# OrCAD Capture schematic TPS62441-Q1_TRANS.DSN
size E; title: TPS62441-Q1 2.75-V to 6-V Dual Step-Down Converter; rev: 1.0; note: Datasheet: SLUSDN9          EVM:SLVUC33; note: Synchronous Step Down Converter; note: with Adjustable Frequency in a QFN Package
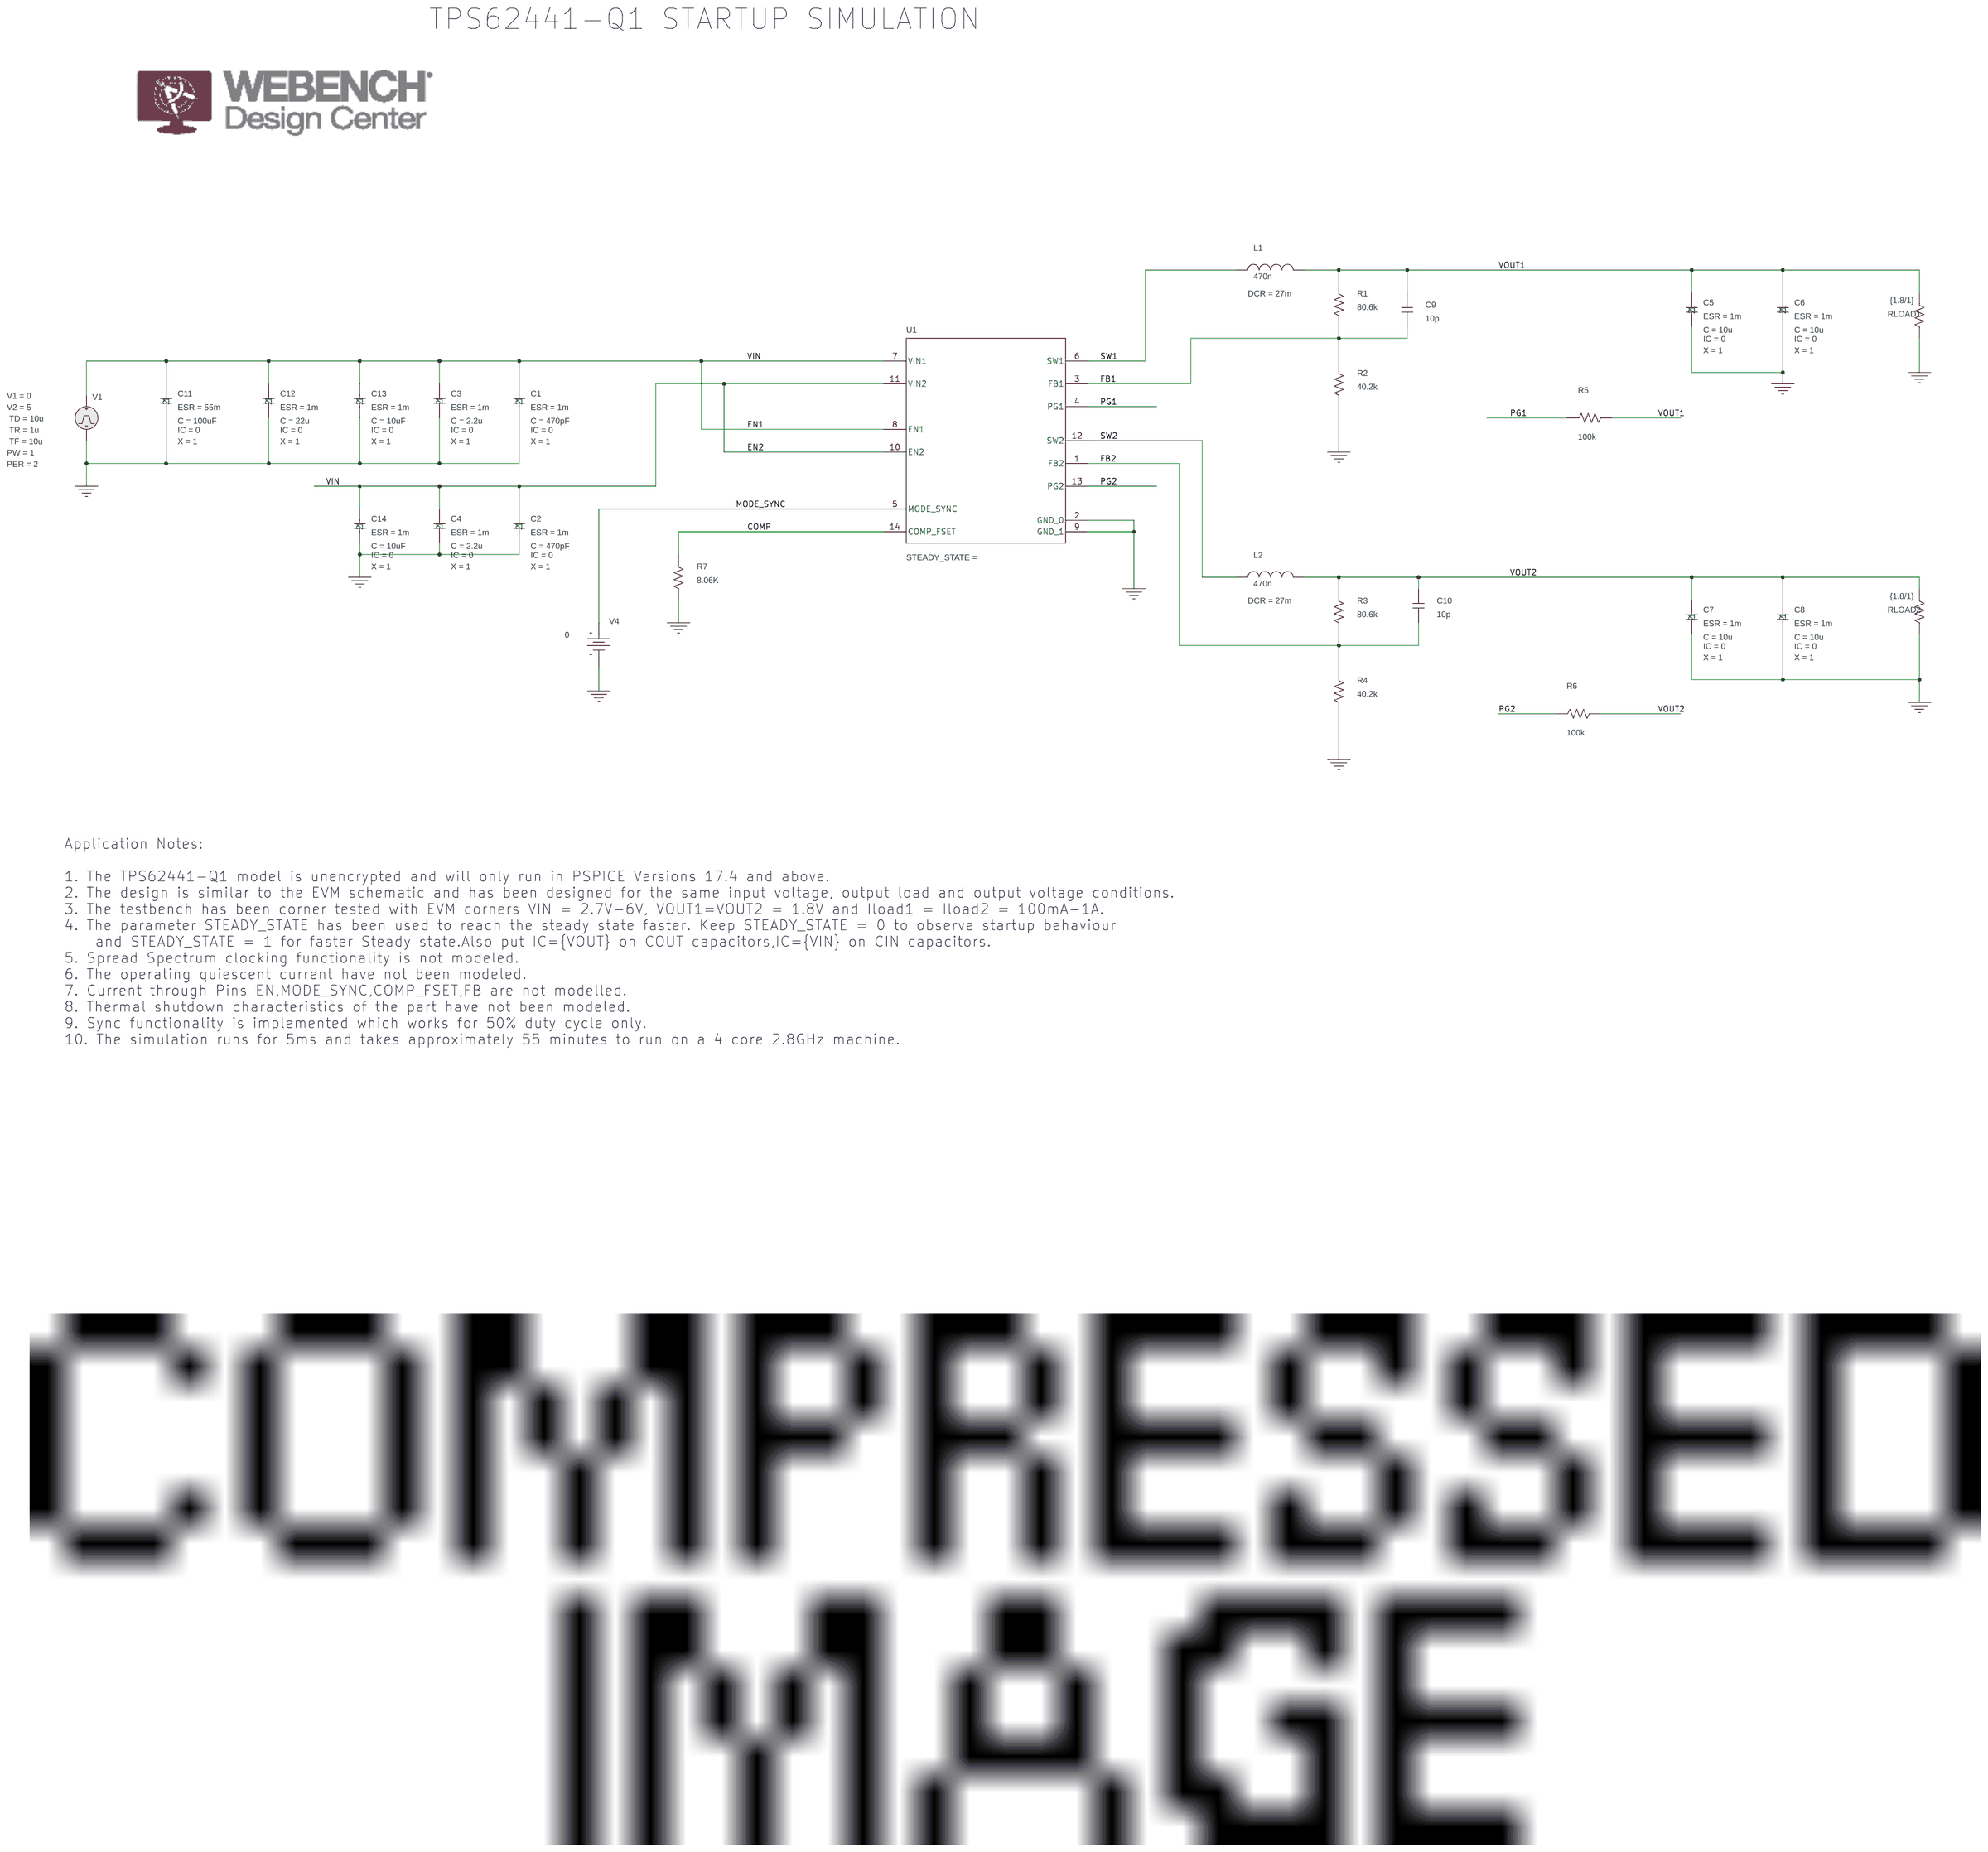
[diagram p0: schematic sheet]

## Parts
C1  CESR
C2  CESR
C3  CESR
C4  CESR
C5  CESR
C6  CESR
C7  CESR
C8  CESR
C9  10p  [RAD/CK05]
C10  10p  [RAD/CK05]
C11  CESR
C12  CESR
C13  CESR
C14  CESR
L1  470n  [DISC/.350x.175/LS.200x.100/.034]
L2  470n  [DISC/.350x.175/LS.200x.100/.034]
R1  80.6k  [AX/RC05]
R2  40.2k  [AX/RC05]
R3  80.6k  [AX/RC05]
R4  40.2k  [AX/RC05]
R5  100k  [AX/RC05]
R6  100k  [AX/RC05]
R7  8.06K  [AX/RC05]
RLOAD1  {1.8/1}  [AX/RC05]
RLOAD2  {1.8/1}  [AX/RC05]
U1  Value  [RQR0014A-MFG]
V1  VPULSE
V4  VDC

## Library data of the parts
C1 = CESR_1_8: C: 470pF; ESR: 1m; IC: 0; PSpiceTemplate: X^@REFDES %1 %2 @MODEL PARAMS: ?C|C=@C||C=10U| ?ESR|ESR=@ESR||ESR=2M| ?IC|IC=@IC||IC=0| ?X|X=@X||X=0|; X: 1
C2 = CESR_1_2: C: 470pF; ESR: 1m; IC: 0; PSpiceTemplate: X^@REFDES %1 %2 @MODEL PARAMS: ?C|C=@C||C=10U| ?ESR|ESR=@ESR||ESR=2M| ?IC|IC=@IC||IC=0| ?X|X=@X||X=0|; X: 1
C3 = CESR_1_5: C: 2.2u; ESR: 1m; IC: 0; PSpiceTemplate: X^@REFDES %1 %2 @MODEL PARAMS: ?C|C=@C||C=10U| ?ESR|ESR=@ESR||ESR=2M| ?IC|IC=@IC||IC=0| ?X|X=@X||X=0|; X: 1
C4 = CESR_1_10: C: 2.2u; ESR: 1m; IC: 0; PSpiceTemplate: X^@REFDES %1 %2 @MODEL PARAMS: ?C|C=@C||C=10U| ?ESR|ESR=@ESR||ESR=2M| ?IC|IC=@IC||IC=0| ?X|X=@X||X=0|; X: 1
C5 = CESR_1: C: 10u; ESR: 1m; IC: 0; PSpiceTemplate: X^@REFDES %1 %2 @MODEL PARAMS: ?C|C=@C||C=10U| ?ESR|ESR=@ESR||ESR=2M| ?IC|IC=@IC||IC=0| ?X|X=@X||X=0|; X: 1
C6 = CESR_1_4: C: 10u; ESR: 1m; IC: 0; PSpiceTemplate: X^@REFDES %1 %2 @MODEL PARAMS: ?C|C=@C||C=10U| ?ESR|ESR=@ESR||ESR=2M| ?IC|IC=@IC||IC=0| ?X|X=@X||X=0|; X: 1
C7 = CESR_1_11: C: 10u; ESR: 1m; IC: 0; PSpiceTemplate: X^@REFDES %1 %2 @MODEL PARAMS: ?C|C=@C||C=10U| ?ESR|ESR=@ESR||ESR=2M| ?IC|IC=@IC||IC=0| ?X|X=@X||X=0|; X: 1
C8 = CESR_1_3: C: 10u; ESR: 1m; IC: 0; PSpiceTemplate: X^@REFDES %1 %2 @MODEL PARAMS: ?C|C=@C||C=10U| ?ESR|ESR=@ESR||ESR=2M| ?IC|IC=@IC||IC=0| ?X|X=@X||X=0|; X: 1
C9 C10 = C
C11 = CESR_1_6: C: 100uF; ESR: 55m; IC: 0; PSpiceTemplate: X^@REFDES %1 %2 @MODEL PARAMS: ?C|C=@C||C=10U| ?ESR|ESR=@ESR||ESR=2M| ?IC|IC=@IC||IC=0| ?X|X=@X||X=0|; X: 1
C12 = CESR_1_9: C: 22u; ESR: 1m; IC: 0; PSpiceTemplate: X^@REFDES %1 %2 @MODEL PARAMS: ?C|C=@C||C=10U| ?ESR|ESR=@ESR||ESR=2M| ?IC|IC=@IC||IC=0| ?X|X=@X||X=0|; X: 1
C13 = CESR_1_1: C: 10uF; ESR: 1m; IC: 0; PSpiceTemplate: X^@REFDES %1 %2 @MODEL PARAMS: ?C|C=@C||C=10U| ?ESR|ESR=@ESR||ESR=2M| ?IC|IC=@IC||IC=0| ?X|X=@X||X=0|; X: 1
C14 = CESR_1_7: C: 10uF; ESR: 1m; IC: 0; PSpiceTemplate: X^@REFDES %1 %2 @MODEL PARAMS: ?C|C=@C||C=10U| ?ESR|ESR=@ESR||ESR=2M| ?IC|IC=@IC||IC=0| ?X|X=@X||X=0|; X: 1
L1 L2 = L: DCR: 27m; IC: 0
R1-R7 RLOAD1 RLOAD2 = R
U1 = TPS62441-Q1RQR_TRANS
V1 = VPULSE: PER: 2; PW: 1; TD: 10u; TF: 10u; TR: 1u; V1: 0; V2: 5
V4 = VDC: DC: 0

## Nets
0: C1.2 C2.2 C3.2 C4.2 C5.2 C6.2 C7.2 C8.2 C11.2 C12.2 C13.2 C14.2 R2.2 R4.2 R7.2 RLOAD1.2 RLOAD2.2 U1.2(GND_0) U1.9(GND_1) V1.2(-) V4.1(-)
COMP: R7.1 U1.14(COMP_FSET)
EN1: C1.1 C2.1 C3.1 C4.1 C11.1 C12.1 C13.1 C14.1 U1.7(VIN1) U1.8(EN1) U1.10(EN2) U1.11(VIN2) V1.1(+)
FB1: C9.1 R1.2 R2.1 U1.3(FB1)
FB2: C10.1 R3.2 R4.1 U1.1(FB2)
MODE_SYNC: U1.5(MODE_SYNC) V4.0(+)
PG1: R5.1 U1.4(PG1)
PG2: R6.1 U1.13(PG2)
SW1: L1.1 U1.6(SW1)
SW2: L2.1 U1.12(SW2)
VOUT1: C5.1 C6.1 C9.2 L1.2 R1.1 R5.2 RLOAD1.1
VOUT2: C7.1 C8.1 C10.2 L2.2 R3.1 R6.2 RLOAD2.1

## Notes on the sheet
- TPS62441-Q1 STARTUP SIMULATION
- Application Notes:
  1. The TPS62441-Q1 model is unencrypted and will only run in PSPICE Versions 17.4 and above.
  2. The design is similar to the EVM schematic and has been designed for the same input voltage, output load and output voltage conditions.
  3. The testbench has been corner tested with EVM corners VIN = 2.7V-6V, VOUT1=VOUT2 = 1.8V and Iload1 = Iload2 = 100mA-1A.
  4. The parameter STEADY_STATE has been used to reach the steady state faster. Keep STEADY_STATE = 0 to observe startup behaviour
      and STEADY_STATE = 1 for faster Steady state.Also put IC={VOUT} on COUT capacitors,IC={VIN} on CIN capacitors.
  5. Spread Spectrum clocking functionality is not modeled.
  6. The operating quiescent current have not been modeled.
  7. Current through Pins EN,MODE_SYNC,COMP_FSET,FB are not modelled.
  8. Thermal shutdown characteristics of the part have not been modeled.
  9. Sync functionality is implemented which works for 50% duty cycle only.
  10. The simulation runs for 5ms and takes approximately 55 minutes to run on a 4 core 2.8GHz machine.
